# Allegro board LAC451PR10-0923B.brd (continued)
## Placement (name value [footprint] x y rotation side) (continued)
H7  -  [H_3P2]  234.75 97.85 0 top
H8  -  [H_3P2]  252.84 78.4 0 top
H10  H3P5  [H_3P5]  202.39 94.48 0 top
H11  -  [H_2P4]  287.35 87.75 0 top
H12  -  [H_2P5]  298.75 39.26 0 top
H13  -  [H_2P4]  300.75 10.65 0 top
H14  -  [H_2P4]  76.75 40.35 0 top
H15  -  [H_2P5]  6.75 39.26 180 bottom
H16  -  [H_2P5]  2.25 46.15 180 bottom
H17  -  [H_2P8]  2.75 53.15 180 bottom
H18  -  [H_2P4]  54.75 138.55 0 top
H19  -  [H_2P4]  120.25 135.15 0 top
H20  -  [H_2P4]  185.25 135.15 0 top
H21  -  [H_2P4]  250.75 139.45 0 top
H22  -  [H_2P4]  301.75 129.65 0 top
H23  -  [H_4P4]  152.75 119.15 0 top
H24  -  [H_2P4]  264.75 39.75 0 top
H25  -  [H_4P4]  157.1 39.2 0 top
H26  -  [H_2P8]  34.75 39.75 0 top
H27  -  [H_3P5]  69.25 85.65 0 top
H28  -  [H_2P3]  236.75 38.04 0 top
H29  -  [H_0P7N]  300.45 124.17 0 top
H30  -  [H_0P9N]  287.4 114.97 0 top
JAPS1  ACES_50506-01841-P01  [ACES_50506-01841-P01_18P-NPM]  183.56 62.77 0 top
JDEG1  ACES_50521-01041-P01  [ACES_50521-01041-P01_10P]  277.6 11.87 270 top
JDIMM1  LOTES_ADDR0107-P005A  [LOTES_ADDR0107-P005A_260P-T]  83.37 49.85 180 bottom
JDIMM2  LOTES_ADDR0107-P005A  [LOTES_ADDR0107-P005A_260P-T]  163.98 49.85 180 bottom
JDOCK1  JAE_WD2F144WBHR500-DT~D  [JAE_WD2F144WBHR500-DT_144P]  134 130.55 0 bottom
JEDP1  ACES_50398-04041-001  [ACES_50398-04041-001_40P]  101.47 117.86 235 bottom
JFAN1  ACES_50271-0040N-001  [ACES_50271-0040N-001_4P]  78.85 97.54 110 bottom
JHDMI1  CONCR_099BKAC19YBLCNF  [CONCR_099BKAC19YBLCNF_19P]  231.8 133.37 0 bottom
JHP1  SINGA_2SJ3095-022111F  [SINGA_2SJ3095-022111F_6P-T]  293 52.52 90 bottom
JIR1  E-T_4251K-F06N-40L  [E-T_4251K-F06N-40L_6P]  54.45 134.05 180 bottom
JKBTP1  ACES_50506-02041-P01  [ACES_50506-02041-P01_20P]  279.8 3.77 90 bottom
JLED1  ACES_50209-00801-001  [ACES_50209-00801-001_8P-T]  289.39 20.75 270 bottom
JLOM1  SANTA_130456-511  [SANTA_130456-511_13P-T]  271.88 129.43 0 bottom
JLPDE1  HB_A531015-SCHR21  [HB_A531015-SCHR21_10P]  256.5 41.6 180 bottom
JMDP1  ACON_MAR2E-2061800~D  [ACON_MAR2E-2061800_20P]  211.65 132.69 180 bottom
JNGFF1  CONCR_213AAAA32FA  [CONCR_213AAAA32FA_67P]  243.6 44.87 0 bottom
JNGFF2  BELLW_80149-3221  [BELLW_80149-3221_67P]  280.28 88.6 90 bottom
JNGFF3  BELLW_80159-2242  [BELLW_80159-2242_67P-T-S]  25.45 34.79 180 bottom
JRTC1  TYCO_2-1775293-2~D  [TYCO_2-1775293-2_2P]  277.38 18.66 180 bottom
JSD1  T-SOL_156-2000302608_NR  [T-SOL_156-2000302608_19P_NR]  273.58 75.5 270 bottom
JSIM1  T-SOL_5-991503004000-6  [T-SOL_5-991503004000-6_8P-T]  290.08 122.02 270 bottom
JSPI1  E-T_6705K-Y20N-00L  [E-T_6705K-Y20N-00L_20P]  199.9 79.61 0 bottom
JSPK1  ACES_50279-0040N-001  [ACES_50279-0040N-001_4P]  288.21 33.97 270 bottom
JTAG1  @SHORT PADS~D  [SHORTPADS]  261.72 78.39 90 top
JUSB1  ACON_TARAV-9R1U91  [ACON_TARAV-9R1U91_9P]  71.75 129.37 0 bottom
JUSB2  ACON_TARAV-9R1U91  [ACON_TARAV-9R1U91_9P]  94.75 129.37 0 bottom
JUSB3  SINGA_2UB4008-900101F  [SINGA_2UB4008-900101F_9P]  290.09 94.5 270 bottom
JUSH1  E-T_6705K-Y26N-00L  [E-T_6705K-Y26N-00L_26P]  296.9 8.43 180 bottom
JXDP1  SAMTE_BSH-030-01-L-D-A  [SAMTE_BSH-030-01-L-D-A_60P]  118.39 126.21 0 bottom
LA2  BLM15BD601SN1D_2P  [MURAT_BLM15BD601SN1D_2P]  283.57 53.25 0 top
LA3  BLM15BD601SN1D_2P  [MURAT_BLM15BD601SN1D_2P]  283.57 45.12 0 top
LA5  BLM15PX600SN1D_2P  [MURAT_BLM15PX600SN1D_2P]  295.55 67.55 0 top
LA6  BLM15PX330SN1D_2P  [MURAT_BLM15PX330SN1D_2P]  281.15 39.78 270 top
LA7  BLM15PX330SN1D_2P  [MURAT_BLM15PX330SN1D_2P]  281.15 33.19 90 top
LA8  BLM15PX330SN1D_2P  [MURAT_BLM15PX330SN1D_2P]  281.15 32.16 270 top
LA9  BLM15PX330SN1D_2P  [MURAT_BLM15PX330SN1D_2P]  281.15 25.69 90 top
LA10  BLM15PX330SN1D_2P  [MURAT_BLM15PX330SN1D_2P]  283.57 52.1 0 top
LA11  BLM15PX330SN1D_2P  [MURAT_BLM15PX330SN1D_2P]  283.57 47.15 0 top
LC1  BLM15HG601SN1D_2P  [MURAT_BLM15HG601SN1D_2P]  190.74 87.9 270 top
LC2  BLM15HG601SN1D_2P  [MURAT_BLM15HG601SN1D_2P]  193.52 95.68 90 top
LED3  LTW-C193DC-C_WHITE  [LED_LTW-C193DC-C_2P]  294.29 120.3 0 top
LI3  EXC24CQ900U_4P  [PANAS_EXC24CQ900U_4P]  69.38 120.01 180 top
LI4  EXC24CQ900U_4P  [PANAS_EXC24CQ900U_4P]  83.49 122.43 180 top
LI7  EXC24CQ900U_4P  [PANAS_EXC24CQ900U_4P]  284.63 100.3 90 top
LL1  4.7UH_BRC2012T4R7MD_20%  [TAIYO_BRC2012T4R7MD_2P]  266.42 93.15 90 top
LV1  BLM15BB221SN1D_2P  [MURAT_BLM15BB221SN1D_2P]  95.55 110.36 325 top
LV3  HCM1012GH900BP_4P  [TAIYO_MCF12102G900-T_4P-NPM]  232.59 127.68 90 top
LV6  HCM1012GH900BP_4P  [TAIYO_MCF12102G900-T_4P-NPM]  234.39 127.68 90 top
LV9  HCM1012GH900BP_4P  [TAIYO_MCF12102G900-T_4P-NPM]  230.8 127.67 90 top
LV12  HCM1012GH900BP_4P  [TAIYO_MCF12102G900-T_4P-NPM]  236.2 127.68 90 top
LV22  BLM15PX181SN1D_2P  [MURAT_BLM15PX181SN1D_2P]  219.24 109.24 180 bottom
LV23  BLM15PX181SN1D_2P  [MURAT_BLM15PX181SN1D_2P]  219.24 110.32 180 bottom
LV24  BLM15PX181SN1D_2P  [MURAT_BLM15PX181SN1D_2P]  221.08 119.42 90 bottom
LV25  BLM15PX181SN1D_2P  [MURAT_BLM15PX181SN1D_2P]  221.08 117.77 90 bottom
LV27  EXC24CQ900U_4P  [PANAS_EXC24CQ900U_4P]  110.52 120.79 90 bottom
LZ1  EXC24CQ900U_4P  [PANAS_EXC24CQ900U_4P]  96.79 113.17 55 top
NOREF  -  []  137.4 153.98 0 top
NOREF#2  -  []  120.25 135.15 0 top
NOREF#3  -  []  125.77 188.5 0 top
NOREF#4  -  []  123.79 104.27 0 top
NOREF#5  -  []  202.39 94.48 0 top
NOREF#6  -  []  252.84 78.4 0 top
NOREF#7  -  []  2.75 53.15 0 top
NOREF#8  -  []  301.75 129.65 0 top
NOREF#9  -  []  54.75 138.55 0 top
NOREF#10  -  []  2.25 46.15 0 top
NOREF#11  -  []  123.79 82.13 0 top
NOREF#12  -  []  142.62 65.03 270 top
NOREF#13  -  []  250.75 139.45 0 top
NOREF#14  -  []  6.75 39.26 0 top
NOREF#15  -  []  183.61 104.27 0 top
NOREF#16  -  []  168.94 55.49 0 top
NOREF#17  -  []  185.25 135.15 0 top
NOREF#18  -  []  183.61 82.13 0 top
NOREF#19  -  []  234.75 97.85 0 top
NOREF#20  -  []  103.11 92.87 0 top
NOREF#21  -  []  298.75 39.26 0 top
NOREF#22  -  []  137.23 281.75 0 top
NOREF#23  -  []  300.75 10.65 0 top
NOREF#24  -  []  287.35 87.75 0 top
NOREF#25  -  []  213.61 96.07 270 top
NOREF#26  -  []  176.25 112.88 0 top
NOREF#27  -  []  144.79 -7.08 0 top
NOREF#28  -  []  76.75 40.35 0 top
NOREF#29  -  []  107.87 58.82 90 top
NOREF#30  -  []  152.75 119.15 0 top
NOREF#31  -  []  197.93 69.03 180 bottom
NOREF#32  -  []  122.38 72.75 180 bottom
NOREF#33  -  []  174.41 57.88 180 bottom
PBATT1  DEREN_40-42251-01001RHF  [DEREN_40-42251-01001RHF_10P-T]  67.87 55.92 235 bottom
PC1  1000P_0603_50V7K  [C_0603]  76.62 102.9 0 top
PC2  1U_0603_10V6K  [C_0603]  284.03 17.98 180 bottom
PC3  2200P_0402_50V7K  [C_0402]  71.27 56.42 0 top
PC4  1500P_0402_50V7K  [C_0402]  72.62 44.53 90 top
PC5  0.022U_0805_50V7K  [C_0805]  69.73 97.95 0 top
PC6  0.1U_0603_25V7K  [C_0603]  71.28 99.48 180 top
PC7  10U_0805_25V6K  [C_0805]  70.08 92.07 270 top
PC100  0.1U_0402_25V6  [C_0402]  218.2 79.69 180 bottom
PC101  0.1U_0402_10V7K  [C_0402]  204.94 81.81 90 top
PC102  0.1U_0603_25V7K  [C_0603]  220.1 90.45 180 top
PC103  2200P_0402_50V7K  [C_0402]  218.2 78.8 180 bottom
PC104  10U_0805_25V6K  [C_0805]  218.04 81.9 180 bottom
PC105  10U_0805_25V6K  [C_0805]  218.04 81.9 180 top
PC106  22U_0805_6.3V6M  [C_0805]  220.65 101.29 0 top
PC107  22U_0805_6.3V6M  [C_0805]  220.65 99.55 0 top
PC108  22U_0805_6.3V6M  [C_0805]  220.66 97.81 0 bottom
PC109  22U_0805_6.3V6M  [C_0805]  220.65 99.55 0 bottom
PC110  22U_0805_6.3V6M  [C_0805]  220.65 101.29 0 bottom
PC111  4.7U_0603_6.3V6K  [C_0603]  214.46 85.8 270 top
PC112  680P_0603_50V7K  [C_0603]  217.35 84.87 180 top
PC113  1000P_0402_50V7K  [C_0402]  213.29 85 180 bottom
PC114  0.1U_0603_25V7K  [C_0603]  213.52 88.25 180 bottom
PC115  0.1U_0402_25V6  [C_0402]  209.61 81.77 180 bottom
PC116  2200P_0402_50V7K  [C_0402]  209.59 80.87 180 bottom
PC117  10U_0805_25V6K  [C_0805]  210.96 83.09 180 bottom
PC118  10U_0805_25V6K  [C_0805]  210.96 83.09 180 top
PC119  4.7U_0603_6.3V6K  [C_0603]  206.79 89.54 180 bottom
PC120  22U_0805_6.3V6M  [C_0805]  207.64 102.8 180 top
PC121  22U_0805_6.3V6M  [C_0805]  207.64 101.05 180 top
PC122  22U_0805_6.3V6M  [C_0805]  207.64 99.31 180 bottom
PC123  22U_0805_6.3V6M  [C_0805]  207.64 101.05 180 bottom
PC124  22U_0805_6.3V6M  [C_0805]  207.64 102.8 180 bottom
PC125  680P_0603_50V7K  [C_0603]  210.11 86.39 270 top
PC126  4.7U_0603_6.3V6K  [C_0603]  206.12 88.26 180 bottom
PC127  1000P_0402_50V7K  [C_0402]  204.77 85.4 90 bottom
PC128  4.7U_0402_6.3V6M  [C_0402]  206.09 82.68 180 bottom
PC201  10U_0805_25V6K  [C_0805]  72.36 62.1 270 top
PC202  10U_0805_25V6K  [C_0805]  70.58 62.1 270 top
PC203  2200P_0402_50V7K  [C_0402]  74.78 62.09 270 top
PC204  0.1U_0402_25V6  [C_0402]  73.76 62.09 270 top
PC205  0.22U_0603_16V7K  [C_0603]  78.08 71.15 90 bottom
PC206  22U_0603_6.3V6M  [C_0603]  73.06 72.93 180 bottom
PC207  1U_0603_10V6K  [C_0603]  79.38 78.76 270 bottom
PC209  1U_0603_10V6K  [C_0603]  79.67 75.2 270 bottom
PC210  0.033U_0402_16V7K  [C_0402]  74.13 76.42 0 top
PC211  680P_0603_50V7K  [C_0603]  76.81 69.44 0 top
PC212  100P_0402_50V8J  [C_0402]  75.85 79.49 90 top
PC213  .1U_0402_16V7K  [C_0402]  76.93 78.22 270 top
PC214  .1U_0402_16V7K  [C_0402]  76.05 78.2 270 top
PC215  22U_0603_6.3V6M  [C_0603]  75.54 58.19 270 bottom
PC216  22U_0603_6.3V6M  [C_0603]  74.27 59.03 270 top
PC217  22U_0603_6.3V6M  [C_0603]  74.27 59.03 270 bottom
PC218  22U_0603_6.3V6M  [C_0603]  75.54 58.19 270 top
PC219  22U_0603_6.3V6M  [C_0603]  76.81 58.19 270 bottom
PC220  22U_0603_6.3V6M  [C_0603]  76.81 58.19 270 top
PC301  0.1U_0402_25V6  [C_0402]  223.94 82.13 90 top
PC302  680P_0603_50V7K  [C_0603]  221.78 86.65 0 bottom
PC303  2200P_0402_50V7K  [C_0402]  223.05 82.13 90 top
PC304  0.1U_0603_25V7K  [C_0603]  227.87 82.58 180 bottom
PC305  10U_0805_25V6K  [C_0805]  223.77 80.87 180 top
PC306  10U_0805_25V6K  [C_0805]  223.77 79.16 180 top
PC307  330P_0402_50V7K  [C_0402]  231.49 84.57 270 top
PC308  47U_0805_6.3V6M  [C_0805]  224.08 89.71 180 top
PC309  47U_0805_6.3V6M  [C_0805]  224.08 87.93 180 top
PC310  22UF_0805_6.3V6M  [C_0805]  222.43 88.91 180 bottom
PC311  22UF_0805_6.3V6M  [C_0805]  222.82 90.71 180 bottom
PC312  4.7U_0603_6.3V6K  [C_0603]  228.95 80.74 270 top
PC313  4.7U_0603_6.3V6K  [C_0603]  229.52 82.14 0 top
PC401  470P_0402_50V7K  [C_0402]  240.7 47.04 270 top
PC402  0.1U_0402_25V6  [C_0402]  242.48 43.21 270 top
PC403  10U_0603_10V6M  [C_0603]  237.63 41.94 180 bottom
PC404  10U_0603_10V6M  [C_0603]  237.63 41.94 180 top
PC406  22U_0603_6.3V6M  [C_0603]  239.43 50.83 0 top
PC407  22U_0603_6.3V6M  [C_0603]  238.02 50.31 0 bottom
PC408  0.1U_0402_25V6  [C_0402]  239.63 42.13 270 top
PC409  2200P_0402_50V7K  [C_0402]  239.63 42.13 270 bottom
PC410  470P_0402_50V7K  [C_0402]  234.05 42.71 180 top
PC411  0.1U_0402_25V6  [C_0402]  243.49 95.21 90 top
PC412  10U_0603_10V6M  [C_0603]  245.15 94.08 0 top
PC413  10U_0603_10V6M  [C_0603]  245.15 92.81 0 top
PC415  22U_0603_6.3V6M  [C_0603]  236.95 89.25 270 top
PC416  22U_0603_6.3V6M  [C_0603]  238.22 89.25 270 top
PC417  0.1U_0402_25V6  [C_0402]  245.64 91.66 0 top
PC418  2200P_0402_50V7K  [C_0402]  245.64 90.78 0 top
PC419  470P_0402_50V7K  [C_0402]  239.74 94.78 0 top
PC420  470P_0402_50V7K  [C_0402]  241.32 87.45 0 top
PC422  22U_0603_6.3V6M  [C_0603]  239.43 49.56 0 top
PC424  22U_0603_6.3V6M  [C_0603]  235.68 88.43 270 top
PC501  22U_0603_6.3V6M  [C_0603]  283.69 4.54 270 top
PC502  22U_0603_6.3V6M  [C_0603]  293.22 3.02 90 top
PC503  68P_0402_50V8J  [C_0402]  292.71 7.6 270 top
PC504  22U_0603_6.3V6M  [C_0603]  282.42 4.54 270 top
PC505  0.1U_0402_16V7K  [C_0402]  287.67 6.8 90 top
PC506  680P_0402_50V7K  [C_0402]  291.11 3.34 0 top
PC507  1U_0402_6.3V6K  [C_0402]  289.1 16.93 180 top
PC508  4.7U_0805_6.3V6K  [C_0805]  290.97 19.85 0 top
PC509  0.01U_0402_25V7K  [C_0402]  297.79 16.87 270 top
PC510  .1U_0402_16V7K  [C_0402]  289.1 15.27 180 top
PC511  22U_0805_6.3V6M  [C_0805]  295.55 19.86 180 top
PC601  680P_0402_50V7K  [C_0402]  89.65 94.4 180 top
PC602  0.1U_0402_25V6  [C_0402]  82.71 86.15 270 bottom
PC603  1U_0603_10V6K  [C_0603]  84.68 88.49 270 bottom
PC604  0.22U_0603_25V7K  [C_0603]  82.65 89.76 90 bottom
PC605  47P_0402_50V8J~D  [C_0402]  79.98 87.49 270 top
PC606  100U_D_20VM_R55M  [C_D]  103.98 108.37 0 bottom
PC608  10U_0805_25V6K  [C_0805]  129.8 111.67 0 top
PC611  0.22U_0603_16V7K  [C_0603]  128.18 113.83 180 top
PC612  10U_0805_25V6K  [C_0805]  129.8 110.84 0.1 bottom
PC613  330P_0402_50V7K  [C_0402]  85.38 86.09 270 bottom
PC614  2200P_0402_50V7K  [C_0402]  88.05 85.17 90 bottom
PC616  33P_0402_50V8J  [C_0402]  86.27 86.09 270 bottom
PC617  1200P_0402_50V7K  [C_0402]  87.35 82.34 270 top
PC618  330P_0402_50V7K  [C_0402]  82.83 82.46 0 bottom
PC619  0.01U_0402_50V7K  [C_0402]  82.83 83.35 0 bottom
PC620  0.082U_0402_16V7K  [C_0402]  84.62 82.44 90 bottom
PC621  680P_0402_50V7K  [C_0402]  84.68 81.43 90 top
PC622  680P_0603_50V7K  [C_0603]  133.07 117 180 top
PC624  0.033U_0402_16V7K  [C_0402]  84.49 80.76 270 bottom
PC625  330P_0402_50V7K  [C_0402]  88.92 86.58 0 bottom
PC626  0.047U_0402_25V7K  [C_0402]  83.6 80.76 270 bottom
PC627  2200P_0402_50V7K  [C_0402]  88.24 82.32 90 top
PC628  10P_0402_50V8J  [C_0402]  86.9 90.53 270 bottom
PC629  2200P_0402_50V7K  [C_0402]  89.76 90.22 270 bottom
PC630  2200P_0402_50V7K  [C_0402]  91.73 91.27 90 top
PC631  1200P_0402_50V7K  [C_0402]  85.11 89.57 0 bottom
PC632  2200P_0402_25V7K  [C_0402]  86.01 92.54 90 top
PC633  6800P_0402_25V7K  [C_0402]  85.95 92.6 90 bottom
PC636  33P_0402_50V8J  [C_0402]  88.92 87.47 0 bottom
PC637  0.033U_0402_16V7K  [C_0402]  84.17 92.6 90 bottom
PC639  1500P_0402_50V7K  [C_0402]  92.67 88.62 0 top
PC640  2200P_0402_50V7K  [C_0402]  87.81 93.51 180 top
PC641  .1U_0402_16V7K  [C_0402]  81.82 79.84 90 bottom
PC642  0.033U_0402_16V7K  [C_0402]  91.72 92.17 0 bottom
PC643  330P_0402_50V7K  [C_0402]  87.79 90.53 270 bottom
PC644  .1U_0402_16V7K  [C_0402]  83.28 93.32 270 bottom
PC645  .1U_0402_16V7K  [C_0402]  92.63 93.06 180 bottom
PC646  0.047U_0402_25V7K  [C_0402]  91.72 91.28 0 bottom
PC647  680P_0402_50V7K  [C_0402]  94.27 87.87 270 bottom
PC649  0.01U_0402_50V7K  [C_0402]  88.67 92.62 0 bottom
PC650  0.082U_0402_16V7K  [C_0402]  86.89 92.62 0 bottom
PC651  330P_0402_50V7K  [C_0402]  93.52 89.51 180 top
PC652  330P_0402_50V7K  [C_0402]  86.89 93.51 0 bottom
PC653  0.082U_0402_16V7K  [C_0402]  91.73 89.49 90 top
PC654  0.01U_0402_50V7K  [C_0402]  93.52 90.39 180 top
PC655  0.22U_0603_16V7K  [C_0603]  101.95 107.1 270 top
PC656  10U_0805_25V6K  [C_0805]  102.5 97.89 0 top
PC657  10U_0805_25V6K  [C_0805]  100.01 101.76 180 bottom
PC658  10U_0805_25V6K  [C_0805]  102.5 98.9 0 bottom
PC659  0.1U_0402_25V6K~D  [C_0402]  99.62 104.94 180 bottom
PC660  2200P_0402_50V7K  [C_0402]  99.62 104.05 180 bottom
PC661  1U_0402_10V6K  [C_0402]  107.61 104.49 0 bottom
PC662  680P_0603_50V7K  [C_0603]  105.95 105.7 180 top
PC671  0.22U_0603_16V7K  [C_0603]  88.03 80.26 0 top
PC672  10U_0805_25V6K  [C_0805]  89.61 77.58 180 bottom
PC673  10U_0805_25V6K  [C_0805]  89.61 77.58 180 top
PC677  1U_0402_10V6K  [C_0402]  96.43 82.67 0 bottom
PC678  680P_0603_50V7K  [C_0603]  96.59 79.43 270 top
PC679  1000P_0402_50V7K  [C_0402]  89.23 78.99 180 bottom
PC680  1000P_0402_50V7K  [C_0402]  99.62 103.16 180 bottom
PC685  1U_0402_10V6K  [C_0402]  127.43 116.49 180 bottom
PC686  10P_0402_50V8J  [C_0402]  99.62 105.83 180 bottom
PC688  10P_0402_50V8J  [C_0402]  89.23 79.88 180 bottom
PC801  10U_0805_25V6K  [C_0805]  32.36 46.81 90 top
PC802  0.1U_0603_25V7K  [C_0603]  13.88 54.64 0 bottom
PC803  10U_0805_25V6K  [C_0805]  41.97 42.26 180 bottom
PC804  10U_0805_25V6K  [C_0805]  40.99 40.83 270 bottom
PC805  22U_0805_25V6M  [C_0805]  40.87 46.62 90 bottom
PC806  10U_0805_25V6K  [C_0805]  41.97 42.26 180 top
PC807  10U_0805_25V6K  [C_0805]  40.99 40.83 270 top
PC808  1U_0603_25V6K  [C_0603]  54.02 54.33 0 bottom
PC809  0.1U_0402_25V6  [C_0402]  56.37 54.53 270 bottom
PC810  0.1U_0402_25V6  [C_0402]  55.43 53.25 180 bottom
PC811  10U_0805_25V6K  [C_0805]  42.77 40.83 270 top
PC812  10U_0805_25V6K  [C_0805]  42.77 40.83 270 bottom
PC813  1U_0603_10V6K  [C_0603]  53.25 51.28 270 top
PC814  10U_0805_25V6K  [C_0805]  57.92 50.74 0 top
PC815  0.1U_0402_25V6  [C_0402]  56.63 55.41 180 bottom
PC816  2200P_0402_50V7K  [C_0402]  60.47 48.48 0 top
PC817  0.1U_0402_25V6  [C_0402]  60.47 47.6 0 top
PC818  22U_0805_25V6M  [C_0805]  59.47 42.86 270 top
PC819  22U_0805_25V6M  [C_0805]  61.25 42.86 270 top
PC820  22U_0805_25V6M  [C_0805]  59.86 44.46 0 top
PC821  0.047U_0603_16V7K  [C_0603]  55.79 51.28 270 top
PC822  22U_0805_25V6M  [C_0805]  59.88 46.24 0 top
PC823  100P_0402_50V8J  [C_0402]  57.31 57.17 90 bottom
PC824  100P_0402_50V8J  [C_0402]  56.42 57.17 90 bottom
PC825  0.1U_0603_25V7K  [C_0603]  30.71 46.96 90 bottom
PC826  10U_0805_25V6K  [C_0805]  30.58 46.81 90 top
PC827  10U_0805_25V6K  [C_0805]  32.36 46.81 90 bottom
PC828  1U_0603_25V6K  [C_0603]  50.28 57.59 180 top
PC829  0.1U_0402_25V6  [C_0402]  53.01 54.83 180 bottom
PC830  0.1U_0402_25V6  [C_0402]  51.23 54.83 90 bottom
PC831  0.1U_0402_25V6  [C_0402]  52.09 55.72 0 bottom
PC832  1000P_0603_50V7K  [C_0603]  50.52 39.72 90 top
PC833  100P_0402_50V8J  [C_0402]  59.28 59.52 90 top
PC834  100P_0402_50V8J  [C_0402]  59.28 62.34 270 top
PC835  22U_0805_25V6M  [C_0805]  40.57 45.73 90 top
PC901  0.1U_0402_25V4Z~D  [C_0402]  93.37 68.61 0 top
PC902  0.47U_0805_25V6K  [C_0805]  6.16 48.81 270 bottom
PC903  0.1U_0402_10V7K  [C_0402]  68.04 72.25 270 top
PC904  1500P_0402_50V7K  [C_0402]  15.03 40.93 180 top
PC905  0.1U_0402_10V7K  [C_0402]  104.11 70.06 90 top
PC906  0.1U_0603_25V7K  [C_0603]  86.01 64.55 180 top
PC907  0.047U_0603_25V7M  [C_0603]  93.38 67.47 0 top
PC908  0.1U_0603_25V7K  [C_0603]  87.22 64.11 270 top
PC1001  22U_0603_6.3V6M  [C_0603]  113.83 107.48 180 bottom
PC1002  22U_0603_6.3V6M  [C_0603]  121.32 112.87 180 top
PC1003  22U_0603_6.3V6M  [C_0603]  116.56 97.13 270 bottom
PC1004  22U_0603_6.3V6M  [C_0603]  154.12 90.29 90 top
PC1005  22U_0603_6.3V6M  [C_0603]  113.83 106.21 180 bottom
PC1006  22U_0603_6.3V6M  [C_0603]  150.5 90.29 90 top
PC1007  22U_0603_6.3V6M  [C_0603]  150.4 96.52 270 top
PC1008  22U_0603_6.3V6M  [C_0603]  121.32 110.33 180 bottom
PC1009  22U_0603_6.3V6M  [C_0603]  155.31 96.52 270 top
PC1010  22U_0603_6.3V6M  [C_0603]  121.32 114.14 180 top
PC1011  22U_0603_6.3V6M  [C_0603]  117.83 97.13 270 bottom
PC1012  22U_0603_6.3V6M  [C_0603]  155.33 90.29 90 top
PC1013  22U_0603_6.3V6M  [C_0603]  151.7 90.29 90 top
PC1014  22U_0603_6.3V6M  [C_0603]  114.91 91.92 90 bottom
PC1015  22U_0603_6.3V6M  [C_0603]  113.26 89.63 270 bottom
PC1016  22U_0603_6.3V6M  [C_0603]  129.61 97.78 270 top
PC1017  22U_0603_6.3V6M  [C_0603]  114.91 89.63 270 bottom
PC1018  22U_0603_6.3V6M  [C_0603]  113.26 91.92 90 bottom
PC1019  22U_0603_6.3V6M  [C_0603]  114.91 91.92 90 top
PC1020  22U_0603_6.3V6M  [C_0603]  145.34 96.01 270 top
PC1021  22U_0603_6.3V6M  [C_0603]  146.55 96.01 270 top
PC1022  22U_0603_6.3V6M  [C_0603]  116.56 91.92 90 bottom
PC1023  22U_0603_6.3V6M  [C_0603]  128.04 95.36 270 top
PC1024  22U_0603_6.3V6M  [C_0603]  133.59 90.4 0 top
PC1025  22U_0603_6.3V6M  [C_0603]  136.13 90.37 0 top
PC1026  22U_0603_6.3V6M  [C_0603]  146.53 93.21 270 top
PC1027  22U_0603_6.3V6M  [C_0603]  116.56 89.63 270 bottom
PC1028  22U_0603_6.3V6M  [C_0603]  139.25 93.61 270 top
PC1029  22U_0603_6.3V6M  [C_0603]  139.25 95.96 270 top
PC1030  1U_0201_6.3V6M  [C_0201]  149.14 92.95 180 top
PC1031  1U_0201_6.3V6M  [C_0201]  155.72 100.11 180 top
PC1032  1U_0201_6.3V6M  [C_0201]  157.41 100.97 180 top
PC1033  1U_0201_6.3V6M  [C_0201]  156.39 98.81 0 top
PC1034  1U_0201_6.3V6M  [C_0201]  154.89 98.65 0 top
PC1035  1U_0201_6.3V6M  [C_0201]  149.14 93.52 180 top
PC1036  1U_0201_6.3V6M  [C_0201]  149.11 98.67 180 top
PC1037  1U_0201_6.3V6M  [C_0201]  154.28 89.49 180 top
PC1038  1U_0201_6.3V6M  [C_0201]  154.94 89.52 0 top
PC1039  1U_0201_6.3V6M  [C_0201]  149.14 91.23 180 top
PC1040  1U_0201_6.3V6M  [C_0201]  143.27 98.76 180 top
PC1041  1U_0201_6.3V6M  [C_0201]  134.42 92.4 270 top
PC1042  1U_0201_6.3V6M  [C_0201]  136.36 95.08 270 top
PC1043  1U_0201_6.3V6M  [C_0201]  137.09 92.41 270 top
PC1044  1U_0201_6.3V6M  [C_0201]  137.65 94.42 90 top
PC1045  1U_0201_6.3V6M  [C_0201]  146.66 98.8 0 top
PC1046  1U_0201_6.3V6M  [C_0201]  137.65 96.93 270 top
PC1047  1U_0201_6.3V6M  [C_0201]  141.43 98.79 180 top
PC1048  1U_0201_6.3V6M  [C_0201]  139.23 98.79 0 top
PC1049  1U_0201_6.3V6M  [C_0201]  134.95 94.62 270 top
PC1050  1U_0201_6.3V6M  [C_0201]  156.28 92.77 0 top
PC1051  1U_0201_6.3V6M  [C_0201]  152.71 98.71 0 top
PC1052  1U_0201_6.3V6M  [C_0201]  158.01 100.97 0 top
PC1053  1U_0201_6.3V6M  [C_0201]  150.16 100.83 180 top
PC1054  1U_0201_6.3V6M  [C_0201]  152.95 100.96 180 top
PC1055  1U_0201_6.3V6M  [C_0201]  145.08 98.8 180 top
PC1056  1U_0201_6.3V6M  [C_0201]  136.36 96.83 270 top
PC1057  22U_0603_6.3V6M  [C_0603]  158.87 94.6 180 top
PC1058  22U_0603_6.3V6M  [C_0603]  141.2 112.62 270 top
PC1059  22U_0603_6.3V6M  [C_0603]  141.2 112.62 270 bottom
PC1060  22U_0603_6.3V6M  [C_0603]  139.93 112.62 270 top
PC1061  22U_0603_6.3V6M  [C_0603]  113.85 107.42 180 top
PC1062  330U_D2_2.5VM_R9M  [C_D2]  117.07 107.77 90 bottom
PC1063  330U_D2_2.5VM_R9M  [C_D2]  117.07 84.77 270 bottom
PC1064  22U_0603_6.3V6M  [C_0603]  155.36 94.1 270 top
PC1065  22U_0603_6.3V6M  [C_0603]  121.32 112.87 180 bottom
PC1066  22U_0603_6.3V6M  [C_0603]  154.09 96.52 270 top
PC1067  22U_0603_6.3V6M  [C_0603]  121.32 111.6 180 bottom
PC1068  22U_0603_6.3V6M  [C_0603]  151.68 94.06 270 top
PC1069  22U_0603_6.3V6M  [C_0603]  152.89 94.06 270 top
PC1070  22U_0603_6.3V6M  [C_0603]  154.1 94.06 270 top
PC1071  22U_0603_6.3V6M  [C_0603]  152.91 90.29 90 top
PC1072  22U_0603_6.3V6M  [C_0603]  150.48 94.06 270 top
PC1073  22U_0603_6.3V6M  [C_0603]  121.32 111.6 180 top
PC1074  22U_0603_6.3V6M  [C_0603]  152.87 96.52 270 top
PC1075  22U_0603_6.3V6M  [C_0603]  115.29 97.13 270 top
PC1076  22U_0603_6.3V6M  [C_0603]  113.83 108.75 180 bottom
PC1077  22U_0603_6.3V6M  [C_0603]  113.83 106.21 180 top
PC1078  22U_0603_6.3V6M  [C_0603]  121.32 114.14 180 bottom
PC1079  22U_0603_6.3V6M  [C_0603]  123.73 110.59 180 bottom
PC1080  22U_0603_6.3V6M  [C_0603]  116.56 97.13 270 top
PC1081  22U_0603_6.3V6M  [C_0603]  114.02 97.13 270 bottom
PC1082  22U_0603_6.3V6M  [C_0603]  115.29 97.13 270 bottom
PC1083  1U_0201_6.3V6M  [C_0201]  156.97 99.53 0 top
PC1084  1U_0201_6.3V6M  [C_0201]  151.23 98.71 0 top
PC1085  1U_0201_6.3V6M  [C_0201]  156.28 90.48 0 top
PC1086  1U_0201_6.3V6M  [C_0201]  149.14 90.66 180 top
PC1087  1U_0201_6.3V6M  [C_0201]  152.13 89.45 180 top
PC1088  1U_0201_6.3V6M  [C_0201]  153.47 100.07 0 top
PC1089  1U_0201_6.3V6M  [C_0201]  145.73 89.53 180 top
PC1090  1U_0201_6.3V6M  [C_0201]  156.97 100.11 0 top
PC1091  1U_0201_6.3V6M  [C_0201]  156.28 91.62 0 top
PC1092  1U_0201_6.3V6M  [C_0201]  156.28 92.2 0 top
PC1093  1U_0201_6.3V6M  [C_0201]  156.28 93.34 0 top
PC1094  1U_0201_6.3V6M  [C_0201]  155.19 100.94 0 top
PC1095  1U_0201_6.3V6M  [C_0201]  153.58 100.95 0 top
PC1096  1U_0201_6.3V6M  [C_0201]  152.88 100.07 180 top
PC1097  1U_0201_6.3V6M  [C_0201]  150.26 100.11 180 top
PC1098  1U_0201_6.3V6M  [C_0201]  149.14 94.09 180 top
PC1099  1U_0201_6.3V6M  [C_0201]  149.14 92.37 180 top
PC1125  1U_0201_6.3V6M  [C_0201]  149.14 91.8 180 top
PC1126  1U_0201_6.3V6M  [C_0201]  156.28 91.05 0 top
PC1127  330U_D2_2.5VM_R9M  [C_D2]  112.58 113.19 180 bottom
PC1128  330U_D2_2.5VM_R9M  [C_D2]  112.37 84.77 270 bottom
PC1129  22U_0603_6.3V6M  [C_0603]  145.32 93.21 270 top
PC1130  22U_0603_6.3V6M  [C_0603]  140.5 95.96 270 top
PC1131  22U_0603_6.3V6M  [C_0603]  131.13 92.98 270 top
PC1132  22U_0603_6.3V6M  [C_0603]  140.5 93.61 270 top
PC1133  22U_0603_6.3V6M  [C_0603]  128.04 97.79 270 top
PC1134  22U_0603_6.3V6M  [C_0603]  132.67 95.37 270 top
PC1135  22U_0603_6.3V6M  [C_0603]  129.61 95.37 270 top
PC1136  22U_0603_6.3V6M  [C_0603]  133.69 89.16 270 top
PC1137  22U_0603_6.3V6M  [C_0603]  114.91 89.63 270 top
PC1138  22U_0603_6.3V6M  [C_0603]  131.13 95.37 270 top
PC1139  22U_0603_6.3V6M  [C_0603]  139.93 114.78 90 top
PC1140  22U_0603_6.3V6M  [C_0603]  141.2 114.78 90 top
PC1141  22U_0603_6.3V6M  [C_0603]  141.2 114.78 90 bottom
PC1142  22U_0603_6.3V6M  [C_0603]  159.7 90.96 180 top
PC1143  22U_0603_6.3V6M  [C_0603]  159.71 89.71 180 top
PC1144  22U_0603_6.3V6M  [C_0603]  158.87 95.8 180 top
PC1145  22U_0603_6.3V6M  [C_0603]  139.93 114.78 90 bottom
PC1146  22U_0603_6.3V6M  [C_0603]  139.93 112.62 270 bottom
PC1147  1U_0201_6.3V6M  [C_0201]  159.47 92.9 180 top
PC1148  1U_0201_6.3V6M  [C_0201]  159.47 93.54 180 top
PC1149  1U_0201_6.3V6M  [C_0201]  160.4 96.6 0 top
PC1150  1U_0201_6.3V6M  [C_0201]  159.5 91.84 0 top
PC1151  1U_0201_6.3V6M  [C_0201]  159.32 99.01 90 top
PC1152  1U_0201_6.3V6M  [C_0201]  160.12 92.79 0 top
PC1153  1U_0201_6.3V6M  [C_0201]  158.73 99.01 90 top
PC1164  1U_0201_6.3V6M  [C_0201]  150.59 98.71 180 top
PC1170  22U_0603_6.3V6M  [C_0603]  151.64 96.52 270 top
PC1171  22U_0603_6.3V6M  [C_0603]  123.73 111.86 180 bottom
PC1172  22U_0603_6.3V6M  [C_0603]  126.15 111.86 180 top
PC1173  22U_0603_6.3V6M  [C_0603]  123.73 111.86 180 top
PC1174  22U_0603_6.3V6M  [C_0603]  126.15 110.59 180 bottom
PC1175  22U_0603_6.3V6M  [C_0603]  118.08 89.63 270 bottom
PC1176  22U_0603_6.3V6M  [C_0603]  118.08 91.92 90 bottom
PC1177  22U_0603_6.3V6M  [C_0603]  132.65 92.93 270 top
PC1178  22U_0603_6.3V6M  [C_0603]  116.56 89.63 270 top
PC1179  22U_0603_6.3V6M  [C_0603]  116.56 91.92 90 top
PC1180  22U_0603_6.3V6M  [C_0603]  128.06 92.98 270 top
PC1181  22U_0603_6.3V6M  [C_0603]  129.6 92.96 270 top
PC1500  1U_0402_6.3V6K  [C_0402]  257.15 46.94 0 top
PC1501  4.7U_0805_6.3V6K  [C_0805]  259.48 45.41 90 top
PC1502  0.01U_0402_25V7K  [C_0402]  251.98 38.97 0 top
PC1503  22U_0805_6.3V6M  [C_0805]  250.68 40.1 90 top
PC1504  .1U_0402_16V7K  [C_0402]  252.87 45.33 180 top
PD1  BAS40CW SOT-323  [BAS40-05W_SC70-3]  283.94 16.11 90 bottom
PD2  -  [TVNST52302AB0_SOT523-3]  67.2 41.53 180 top
PD3  -  [TVNST52302AB0_SOT523-3]  65.12 41.53 180 top
PD4  SDMK0340L-7-F_SOD323-2~D  [RB751V-40_SOD323-2]  69.39 40.42 0 top
PD6  -  [PESD5V0U2BT_SOT23-3]  76.2 111.92 90 top
PD7  -  [PESD5V0U2BT_SOT23-3]  79.27 107.46 0 top
PD801  SDMK0340L-7-F_SOD323-2~D  [SDMK0340L-7-F_SOD323-2]  59.73 56.42 0 top
PD802  SDMK0340L-7-F_SOD323-2~D  [SDMK0340L-7-F_SOD323-2]  59.73 58.2 0 top
PD803  SDMK0340L-7-F_SOD323-2~D  [SDMK0340L-7-F_SOD323-2]  59.73 54.64 0 top
PD901  -  [BAT54CW_SOT323-3]  83.36 74.37 0 top
PD902  -  [PDS5100H-13_POWERDI5-3]  26.75 46.52 180 bottom
PD903  -  [PDS5100H-13_POWERDI5-3]  12.8 49.29 270 top
PD904  SDMK0340L-7-F_SOD323-2~D  [SDMK0340L-7-F_SOD323-2]  12.67 39.98 90 top
PD905  -  [BAT54CW_SOT323-3]  9.49 57.7 90 top
PH601  470K_0402_5%_ TSM0B474J4702RE  [R_0402]  93.25 82.43 180 bottom
PH602  10K_0402_5%_ERTJ0ER103J  [R_0402]  101.66 84.97 0 bottom
PH603  470K_0402_5%_ TSM0B474J4702RE  [R_0402]  108.55 98.46 180 bottom
PH604  10KB_0402_5%_ERTJ0ER103J  [R_0402]  136.43 118.12 270 bottom
PH605  10KB_0402_5%_ERTJ0ER103J  [R_0402]  112.81 96.29 90 bottom
PJP1  PAD-OPEN 1X3M  [JUMP_43X118]  68.43 110.42 90 top
PJP6  PAD-OPEN1X2M  [JUMP_43X79]  297.21 76.76 90 top
PJP9  PAD-OPEN1X1M  [JUMP_43X39]  275.56 71.59 90 top
PJP10  PAD-OPEN1X1M  [JUMP_43X39]  275.69 66.28 270 top
PJP11  PAD-OPEN1X1M  [JUMP_43X39]  221.29 63.57 180 top
PJP12  PAD-OPEN1X2M  [JUMP_43X79]  245.46 50.41 90 top
PJP13  PAD-OPEN1X1M  [JUMP_43X39]  283 112.81 180 top
PJP14  PAD-OPEN1X1M  [JUMP_43X39]  264.69 58.71 0 top
PJP15  PAD-OPEN1X1M  [JUMP_43X39]  263.19 58.71 180 top
PJP16  PAD-OPEN1X1M  [JUMP_43X39]  282.17 11.29 270 top
PJP18  PAD-OPEN1X2M  [JUMP_43X79]  83.41 114.5 270 bottom
PJP19  PAD-OPEN1X1M  [JUMP_43X39]  192.97 82.52 180 top
PJP20  PAD-OPEN1X1M  [JUMP_43X39]  198.27 84.29 0 top
PJP21  PAD-OPEN1X2M  [JUMP_43X79]  83.41 121.79 90 bottom
PJP22  PAD-OPEN1X3M  [JUMP_43X118]  246.23 44.27 270 top
PJP23  PAD-OPEN1X3M  [JUMP_43X118]  283.31 106.17 180 top
PJP25  PAD-OPEN1X1M  [JUMP_43X39]  211.68 105.94 90 top
PJP26  PAD-OPEN1X2M  [JUMP_43X79]  267.5 72.89 90 top
PJP27  PAD-OPEN1X1M  [JUMP_43X39]  120.57 130.02 180 top
PJP29  PAD-OPEN1X1M  [JUMP_43X39]  89.46 108.75 180 top
PJP30  PAD-OPEN1X1M  [JUMP_43X39]  278.1 66.28 270 top
PJP31  PAD-OPEN1X1M  [JUMP_43X39]  279.12 72.5 270 top
PJP32  PAD-OPEN1X1M  [JUMP_43X39]  159.1 112.51 90 bottom
PJP34  PAD-OPEN1X2M  [JUMP_43X79]  22.53 39.35 90 top
PJP35  PAD-OPEN1X3M  [JUMP_43X118]  169.16 117.76 0 top
PJP36  PAD-OPEN1X2M  [JUMP_43X79]  26.38 39.35 90 top
PJP100  PAD-OPEN 1X2M~D  [JUMP_43X79]  220.58 79.54 90 bottom
PJP101  PAD-OPEN 1X2M~D  [JUMP_43X79]  211.95 79.94 90 bottom
PJP102  -  [JUMP_43X118]  217.33 99.56 90 bottom
PJP103  -  [JUMP_43X118]  211.76 99.7 90 bottom
PJP201  JUMP_1X3M  [JUMP_43X118]  83.24 58.52 0 top
PJP202  PAD-OPEN 1X2M~D  [JUMP_43X79]  67.37 63.03 0 top
PJP203  PAD-OPEN1X1M  [JUMP_43X39]  74.78 72.31 270 bottom
PJP204  JUMP_1X3M  [JUMP_43X118]  83.24 53.31 0 top
PJP205  PAD-OPEN1X1M  [JUMP_43X39]  72.82 74.84 180 bottom
PJP301  PAD-OPEN 1X2M~D  [JUMP_43X79]  226.37 78.96 90 top
PJP302  -  [JUMP_43X118]  224.89 92.96 90 bottom
PJP401  -  [JUMP_43X79]  237.72 52.7 90 top
PJP402  -  [JUMP_43X79]  234.96 90.84 180 top
PJP403  PAD-OPEN1X1M  [JUMP_43X39]  239.1 45.03 270 bottom
PJP404  PAD-OPEN1X1M  [JUMP_43X39]  246.81 89.19 180 top
PJP501  -  [JUMP_43X79]  296.18 4.23 180 top
PJP502  -  [JUMP_43X79]  280.56 3.93 180 top
PJP503  PAD-OPEN1X1M  [JUMP_43X39]  288.69 20.1 0 top
PJP504  PAD-OPEN1X1M  [JUMP_43X39]  296.85 20.17 0 top
PJP601  PAD-OPEN 4X4M  [JUMP_43X118]  97.04 98.21 180 bottom
PJP602  PAD-OPEN 1X2M~D  [JUMP_43X79]  96.75 90.04 90 bottom
PJP603  PAD-OPEN1X1M  [JUMP_43X39]  128.38 110.65 180 bottom
PJP801  PAD-OPEN 4X4M  [JUMP_43X118-NPM]  61.24 54.87 235 bottom
PJP1500  PAD-OPEN1X1M  [JUMP_43X39]  249.11 39.65 180 top
PJP1501  PAD-OPEN1X1M  [JUMP_43X39]  262.52 45.53 180 top
PJPDC1  CVILU_CI0805M1HRC-NH  [CVILU_CI0805M1HRC-NH_5P-T]  77.25 103.8 195 bottom
PL1  FBMJ4516HS720NT_2P  [TAIYO_FBMJ4516HS720NT_2P]  73.25 102.85 270 top
PL2  FBMJ4516HS720NT_2P  [TAIYO_FBMJ4516HS720NT_2P]  71.28 52.36 0 top
PL3  FBMJ4516HS720NT_2P  [TAIYO_FBMJ4516HS720NT_2P]  71.28 54.64 0 top
PL4  BLM15AG102SN1D_2P  [MURAT_BLM15AG102SN1D_2P]  72.36 113.74 270 top
PL100  1.5UH_PCMC063T-1R5MN_9A_20%  [CYNTE_PCMC063T-1R5MN_2P]  216.84 90.53 90 bottom
PL101  2.2UH +-20% 7.8A 7X7X3 MOLDING  [CYNTE_PCMC063T-1R5MN_2P]  209.75 90.72 90 bottom
PL201  1UH_11A_20%  [PANAS_ETQP3W2R2WFN_2P]  73.89 61.91 270 bottom
PL301  0.68UH +-20% 7.9A  [MAG_MMD-05CZ-R68M-X2L_2P]  226.19 85.19 90 bottom
PL402  1UH_1277AS-H-1R0N-P2_3.3A_30%  [MAG_MLV-FY12N1R0M-O1L_2P]  237.14 48.34 90 top
PL404  1UH_1277AS-H-1R0N-P2_3.3A_30%  [MAG_MLV-FY12N1R0M-O1L_2P]  237.69 93.01 270 top
PL501  1UH_1277AS-H-1R0N-P2_3.3A_30%  [MAG_MLV-FY12N1R0M-O1L_2P]  287.56 4.13 180 top
PL601  1UH +-20% 6.6A  [MAG_MMD-05CZ-R68M-X2L_2P]  133.18 113.83 0 bottom
PL602  FBMA-L11-453215800LMA90T_2P  [KC_FBMA-L11-4532158_2P-NPM]  98.39 98.21 180 bottom
PL603  0.15UH_MMD06CZER15MG_37A_20%  [MAG_MMD06CZER15MG_4P]  117.57 101.51 180 bottom
PL604  0.15UH_MMD06CZER15MG_37A_20%  [MAG_MMD06CZER15MG_4P]  108.13 80.44 180 bottom
PL801  3.3UH_10A_20%  [TOKO_FDVE1040-H-3R3M-P3_2P]  44.6 46.45 0 bottom
PL802  1UH +-20% 6.6A  [MAG_MMD-05CZ-R68M-X2L_2P]  59.75 52.74 55 bottom
PQ1  DCX124EK-7-F PNP/NPN_SC74-6~D  [IMD2AT-108_SC74-6]  77.5 98.02 270 top
PQ2  LP2301ALT1G_SOT23-3  [SI2301CDS-T1-GE3_SOT23-3]  70.18 42.63 0 top
PQ3  -  [FDV301N-G_SOT23-3]  73.16 118.46 270 top
PQ4  MMBT3904WT1G NPN SC70-3  [MMST3904-7-F_SOT323-3]  68.68 114.78 0 top
PQ5  AON7401 1P DFN3*3  [FDMC6679AZ_MLP8-5]  71.94 96.43 180 top
PQ201  -  [AON6932A_DFN5X6-8-7]  70.38 67.49 270 top
PQ501  AON7934_DFN3X3A-8-10  [AON7934_DFN3X3A8-10]  130.61 112.45 180 bottom
PQ801  DMP3056L-7 1P SOT23-3  [NTR4502PT1G_SOT23-3]  16.41 52.51 90 bottom
PQ802  -  [SI4835DDY-T1-GE3_SO8]  11.78 52.64 180 bottom
PQ803  DMP3056L-7 1P SOT23-3  [NTR4502PT1G_SOT23-3]  16.41 48.52 90 bottom
PQ804  DMP3056L-7 1P SOT23-3  [NTR4502PT1G_SOT23-3]  17.17 46.4 270 top
PQ805  DMP3056L-7 1P SOT23-3  [NTR4502PT1G_SOT23-3]  17.17 50.4 270 top
PQ808  AON6992 2N DFN5X6D  [AON6932A_DFN5X6-8-7]  58.09 43.1 90 top
PQ809  L2N7002WT1G_SC70-3  [DMN65D8LW-7_SOT323-3]  62.27 59.72 270 bottom
PQ901  -  [FDS6679AZ-G_SO8]  21.05 39.52 180 bottom
PQ902  S TR DMN65D8LDW-7 2N SOT363-6  [DMN65D8LDW-7_SOT363-6]  64.17 70.28 270 top
PQ903  -  [SI4835DDY-T1-GE3_SO8]  28.19 43.2 270 bottom
PQ904  -  [FDS6679AZ-G_SO8]  7.9 49.84 0 bottom
PQ905  AON7401 1P DFN3*3  [FDMC6679AZ_MLP8-5]  15.36 43.15 180 bottom
PQ906  L2N7002WT1G_SC70-3  [DMN65D8LW-7_SOT323-3]  95.93 75.26 270 top
PQ907  S TR DMN65D8LDW-7 2N SOT363-6  [DMN65D8LDW-7_SOT363-6]  103.03 72.54 90 top
PQ908  L2N7002WT1G_SC70-3  [DMN65D8LW-7_SOT323-3]  16.86 40.23 180 top
PQ909  LP2301ALT1G_SOT23-3  [SI2301CDS-T1-GE3_SOT23-3]  97.61 73.59 180 top
PQ910  -  [DMP3099L-7_SOT23-3]  9.98 54.14 270 top
PQ911  S TR DMN65D8LDW-7 2N SOT363-6  [DMN65D8LDW-7_SOT363-6]  8.17 57.05 90 top
PR1  1M_0402_5%  [R_0402]  77.75 101.25 0 top
PR2  1K_0402_5%  [R_0402]  281.1 16.25 270 bottom
PR3  100K_0402_5%  [R_0402]  70.28 39.15 180 top
PR4  0_0402_5%  [R0402_0OHM]  72.62 42.76 90 top
PR5  0_0402_5%  [R_0402]  73.43 120.94 0 top
PR6  2.2K_0402_5%  [R_0402]  76.98 120.94 0 top
PR7  33_0402_5%  [R_0402]  75.21 120.94 0 top
PR8  100K_0402_1%  [R_0402]  70.44 116.37 0 top
PR9  10K_0402_1%  [R_0402]  71.35 114.51 90 top
PR10  15K_0402_1%  [R_0402]  71.36 117.26 180 top
PR11  10K_0402_5%  [R_0402]  70.46 115.43 270 top
PR12  100K_0402_5%  [R_0402]  71.73 91.17 270 top
PR13  4.7K_0805_5%  [R_0805]  75.35 98.87 270 top
PR14  10K_0402_5%  [R_0402]  80.49 101.24 90 top
PR15  1M_0402_5%  [R_0402]  79.6 101.24 90 top
PR100  0_0603_5%  [R0603_0OHM]  219.99 87.8 90 top
PR101  0_0402_5%  [R_0402]  205.03 79.22 270 top
PR102  499K_0402_1%  [R_0402]  214.35 79.69 270 bottom
PR103  499K_0402_1%  [R_0402]  214.34 80.56 0 bottom
PR104  0_0402_5%  [R0402_0OHM]  213.42 85.85 270 top
PR105  0_0402_5%  [R0402_0OHM]  212.54 85.85 270 top
PR106  4.7_1206_5%  [R_1206]  217.14 89.65 270 top
PR107  100K_0402_5%  [R_0402]  215.24 82.29 90 bottom
PR108  1K_0402_5%  [R_0402]  212.38 85.89 0 bottom
PR109  150K_0402_1%  [R_0402]  214.18 85.92 270 bottom
PR110  150K_0402_1%  [R_0402]  213.29 84.11 180 bottom
PR111  0_0603_5%  [R0603_0OHM]  212.13 87.02 0 bottom
PR112  4.7_1206_5%  [R_1206]  209.4 87.88 0 top
PR113  100K_0402_5%  [R_0402]  207.29 83.5 270 bottom
PR114  0_0402_5%  [R0402_0OHM]  205.18 80.89 0 bottom
PR115  150K_0402_1%  [R_0402]  205.7 86.32 270 bottom
PR116  1M_0402_1%  [R_0402]  206.09 81.78 180 bottom
PR117  1K_0402_5%  [R_0402]  204.78 87.19 0 bottom
PR118  150K_0402_1%  [R_0402]  205.17 84.49 270 bottom
PR119  0_0402_5%  [R0402_0OHM]  207.39 79.19 270 top
PR120  0_0402_5%  [R0402_0OHM]  206.47 79.19 270 top
PR201  2.2_0603_5%  [R_0603]  80.62 77.38 90 bottom
PR202  2.2_0603_5%  [R_0603]  76.81 71.15 90 bottom
PR203  5.1K_0402_1%  [R_0402]  80.19 76.23 180 bottom
PR204  4.7_1206_5%  [R_1206]  72.93 69.44 0 top
PR205  5.1_0603_5%  [R_0603]  80.89 73.81 90 bottom
PR206  12K_0402_1%  [R_0402]  76.74 79.49 90 top
PR207  453K_0402_1%  [R_0402]  77.95 80.37 270 bottom
PR208  0_0402_5%  [R0402_0OHM]  77.06 80.37 270 bottom
PR209  20K_0402_1%  [R_0402]  75.16 78.2 270 top
PR210  0_0402_5%  [R0402_0OHM]  76.17 80.37 270 bottom
PR301  0_0402_5%  [R_0402]  230.59 89.06 0 top
PR302  1M_0402_1%  [R_0402]  230.59 88.17 0 top
PR303  4.7_1206_5%  [R_1206]  222.6 82.65 90 bottom
PR304  0_0603_5%  [R0603_0OHM]  225.46 82.58 180 bottom
PR306  6.65K_0402_1%  [R_0402]  231.51 85.51 180 top
PR307  0_0402_5%  [R_0402]  231.51 86.39 180 top
PR308  1K_0402_5%  [R_0402]  230.6 83.65 90 top
PR310  0_0402_5%  [R_0402]  230.59 87.28 0 top
PR311  10K_0402_1%  [R_0402]  229.72 84.57 270 top
PR312  0_0402_5%  [R0402_0OHM]  229.72 88.16 90 top
PR402  0_0402_5%  [R0402_0OHM]  242.5 44.08 180 top
PR403  1M_0402_1%  [R_0402]  241.59 43.21 270 top
PR404  0_0402_5%  [R_0402]  242.48 45.89 270 top
PR405  4.7_0603_5%  [R_0603]  239.43 48.29 0 top
PR406  0_0402_5%  [R0402_0OHM]  245.27 96.12 270 top
PR407  1M_0402_1%  [R_0402]  244.38 95.21 90 top
PR408  0_0402_5%  [R_0402]  244.88 86.52 90 top
PR409  4.7_0603_5%  [R_0603]  237.4 94.78 0 top
PR410  0_0402_5%  [R_0402]  242.61 96.12 270 top
PR411  0_0402_5%  [R_0402]  243.99 86.52 90 top
PR412  0_0402_5%  [R0402_0OHM]  234.05 43.6 180 top
PR413  10K_0402_1%  [R_0402]  232.06 40.81 0 top
PR414  10K_0402_1%  [R_0402]  232.06 39.87 270 top
PR415  10K_0402_1%  [R_0402]  233.94 41.8 270 top
PR416  10K_0402_1%  [R_0402]  232.97 38.96 90 top
PR417  10K_0402_1%  [R_0402]  243.1 86.52 90 top
PR418  10K_0402_1%  [R_0402]  245.77 86.52 90 top
PR419  10K_0402_1%  [R_0402]  243.05 88.31 180 top
PR420  10K_0402_1%  [R_0402]  246.69 87.44 270 top
PR421  100_0402_1%  [R_0402]  233.13 45.37 0 top
PR422  0_0402_5%  [R0402_0OHM]  234.05 44.48 180 top
PR423  0_0402_5%  [R0402_0OHM]  240.33 88.81 180 top
PR424  100K_0402_1%  [R_0402]  240.33 87.85 180 top
PR425  0_0402_5%  [R_0402]  241.59 45.89 270 top
PR426  0_0402_5%  [R_0402]  241.72 96.12 270 top
PR427  0_0402_5%  [R0402_0OHM]  232.98 41.74 180 top
PR428  1M_0402_1%  [R_0402]  241.32 86.56 0 top
PR501  20K_0402_1%  [R_0402]  293.6 7.6 270 top
PR502  4.7_0603_5%  [R_0603]  288.71 3.34 0 top
PR504  0_0402_5%  [R0402_0OHM]  285.89 7.72 270 top
PR505  1M_0402_1%  [R_0402]  286.78 6.8 90 top
PR506  10K_0402_1%  [R_0402]  294.49 6.69 90 top
PR507  100K_0402_5%  [R_0402]  288.19 13.5 0 top
PR508  8.87K_0402_1%  [R_0402]  298.68 16.87 270 top
PR509  47K_0402_5%  [R_0402]  289.1 14.39 180 top
PR510  10.2K_0402_1%  [R_0402]  297.84 15.02 0 top
PR511  47K_0402_5%  [R_0402]  289.1 12.58 180 top
PR601  45.3_0402_1%  [R_0402]  82.73 87.03 180 bottom
PR602  0_0402_5%  [R0402_0OHM]  84.24 89.56 90 bottom
PR603  0_0402_5%  [R0402_0OHM]  81.57 89.75 90 bottom
PR604  75_0402_1%  [R_0402]  82.73 87.92 180 bottom
PR605  100_0402_1%  [R_0402]  82.73 88.81 180 bottom
PR606  0_0402_5%  [R0402_0OHM]  79.46 87.03 0 bottom
PR607  0_0402_5%  [R0402_0OHM]  79.46 87.92 0 bottom
PR608  78.7K_0402_1%  [R_0402]  82.73 89.82 180 top
PR609  0_0402_5%  [R0402_0OHM]  79.46 88.81 0 bottom
PR610  10K_0402_1%  [R_0402]  84.67 83.22 0 top
PR611  48.7K_0402_1%  [R_0402]  82.73 90.71 180 top
PR612  1.91K_0402_1%  [R_0402]  81.81 86.14 0 top
PR613  90.9K_0402_1%  [R_0402]  84.49 86.09 270 bottom
PR614  0_0402_5%  [R0402_0OHM]  81.81 85.25 0 top
PR616  0_0402_5%  [R0402_0OHM]  81.81 84.36 0 top
PR617  4.3K_0402_1%  [R_0402]  87.16 86.09 270 bottom
PR618  49.9_0402_1%  [R_0402]  81.81 87.16 0 top
PR619  2.2_0603_5%  [R_0603]  129.19 113.83 0 top
PR620  0_0402_5%  [R0402_0OHM]  82.84 82.38 90 top
PR621  316_0402_1%  [R_0402]  86.46 81.43 90 top
PR622  1.96K_0402_1%  [R_0402]  87.36 83.22 180 top
PR623  2K_0402_1%  [R_0402]  85.57 81.43 90 top
PR624  3.65K_0603_1%  [R_0603]  134.53 117.34 180 bottom
PR625  0_0402_5%  [R0402_0OHM]  81.81 88.05 0 top
PR626  10_0402_1%  [R_0402]  81.81 88.93 0 top
PR627  4.7_1206_5%  [R_1206]  131.86 115.29 0 top
PR628  4.42K_0402_1%  [R_0402]  99.88 84.97 0 bottom
PR629  88.7K_0402_1%  [R_0402]  88.92 85.7 0 bottom
PR630  7.32K_0402_1%  [R_0402]  86.03 90.46 180 bottom
PR631  27.4K_0402_1%  [R_0402]  83.79 82.32 90 top
PR632  1K_0402_1%  [R_0402]  89.14 81.44 180 top
PR633  11K_0402_1%  [R_0402]  82.71 80.76 270 bottom
PR635  10K_0402_1%  [R_0402]  91.6 87.87 270 bottom
PR636  1.24K_0402_1%  [R_0402]  85.13 92.54 90 top
PR638  374_0402_1%  [R_0402]  89.13 82.32 90 top
PR639  5.49K_0402_1%  [R_0402]  88.92 88.36 0 bottom
PR640  340_0402_1%  [R_0402]  92.61 91.28 0 top
PR641  1K_0402_1%  [R_0402]  86.03 94.33 180 top
PR642  2.61K_0402_1%  [R_0402]  134.67 118.45 0 bottom
PR643  11K_0402_1%  [R_0402]  85.06 93.52 270 bottom
PR644  1K_0402_1%  [R_0402]  92.61 92.17 0 top
PR645  316_0402_1%  [R_0402]  93.58 87.73 180 top
PR646  316_0402_1%  [R_0402]  88.68 92.6 90 top
PR647  27.4K_0402_1%  [R_0402]  93.39 87.85 180 bottom
PR648  1.37K_0402_1%  [R_0402]  91.79 88.63 270 top
PR649  1.62K_0402_1%  [R_0402]  87.81 92.62 180 top
PR650  2K_0402_1%  [R_0402]  93.36 86.05 90 bottom
PR651  133K_0402_1%  [R_0402]  88.68 90.53 270 bottom
PR652  2K_0402_1%  [R_0402]  89.57 92.6 90 top
PR653  20M_0402_5%  [R_0402]  90.87 91.96 270 bottom
PR654  20M_0402_5%  [R_0402]  84.84 91.76 0 bottom
PR656  11K_0402_1%  [R_0402]  91.72 90.39 0 bottom
PR657  4.42K_0402_1%  [R_0402]  110.2 95.92 0 bottom
PR658  20M_0402_5%  [R_0402]  83.41 80.5 0 top
PR659  0_0402_5%  [R0402_0OHM]  107.64 105.43 0 bottom
PR660  2.2_0603_5%  [R_0603]  103.16 107.1 270 top
PR661  3.65K_0603_1%  [R_0603]  111.61 97.06 180 bottom
PR662  5.11K_0402_1%  [R_0402]  102.38 105.32 0 bottom
PR663  4.7_1206_5%  [R_1206]  107.54 102.97 90 top
PR671  0_0402_5%  [R0402_0OHM]  95.59 82.66 180 bottom
PR672  2.2_0603_5%  [R_0603]  88.03 79.05 0 top
PR673  0_0402_5%  [R0402_0OHM]  100.51 81.24 90 top
PR674  3.65K_0603_1%  [R_0603]  99.37 82.43 270 top
PR676  4.7_1206_5%  [R_1206]  100.63 78.95 180 top
PR678  100_0402_1%  [R_0402]  79.98 85.71 270 top
PR679  0_0402_5%  [R0402_0OHM]  127.24 114.97 180 top
PR680  5.11K_0402_1%  [R_0402]  90.56 82.43 0 bottom
PR801  100K_0402_1%  [R_0402]  53.76 57.17 90 bottom
PR802  0.01_1206_1%  [R_1206_4P-D]  14.01 48.55 90 bottom
PR803  100K_0402_1%  [R_0402]  6.45 56.73 90 bottom
PR804  0_0402_5%  [R0402_0OHM]  17.21 55.1 180 bottom
PR805  100_0402_1%  [R_0402]  20.29 49.74 90 bottom
PR806  0_0402_5%  [R0402_0OHM]  21.17 50.64 0 bottom
PR807  0_0402_5%  [R0402_0OHM]  21.17 49.75 0 bottom
PR808  100K_0402_1%  [R_0402]  21.05 46.31 90 top
PR809  100K_0402_1%  [R_0402]  21.05 49.01 270 top
PR810  0_0402_5%  [R0402_0OHM]  21.94 47.2 90 top
PR811  10_1206_5%  [R_1206]  60.55 52.71 180 top
PR812  34K_0402_1%  [R_0402]  58.2 57.17 90 bottom
PR813  6.49K_0402_1%  [R_0402]  56.63 56.3 180 bottom
PR814  2.2_0603_5%  [R_0603]  54.52 51.28 270 top
PR815  0_0402_5%  [R0402_0OHM]  58.07 58.21 270 top
PR816  0_0402_5%  [R0402_0OHM]  57.31 60.37 270 top
PR817  154K_0402_1%  [R_0402]  54.65 58.09 270 bottom
PR818  100_0402_1%  [R_0402]  54.65 60.37 270 top
PR819  0_0402_5%  [R0402_0OHM]  56.42 60.37 270 top
PR820  0_0402_5%  [R0402_0OHM]  55.53 60.37 270 top
PR821  10K_0402_1%  [R_0402]  51.28 52.05 270 top
PR822  31.6K_0402_1%  [R_0402]  55.53 57.17 90 bottom
PR823  0.01_1206_1%  [R_1206_4P-D]  34.41 46.22 0 bottom
PR824  4.7_1206_5%  [R_1206]  52.04 40.17 0 top
PR825  4.02K_0402_1%  [R_0402]  50.66 55.22 180 top
PR826  10_0603_1%  [R_0603]  50.29 56.33 180 top
PR827  1K_0402_5%  [R_0402]  52.69 57.69 180 bottom
PR828  0_0402_5%  [R0402_0OHM]  49.36 58.77 0 top
PR829  154K_0402_1%  [R_0402]  51.78 56.8 0 bottom
PR830  649K_0402_1%  [R_0402]  62.28 60.44 270 top
PR831  100K_0402_1%  [R_0402]  60.17 60.44 270 top
PR832  3M_0402_5%  [R_0402]  61.06 59.52 90 top
PR833  0_0402_5%  [R0402_0OHM]  61.06 62.34 270 top
PR834  10K_0402_1%  [R_0402]  60.17 61.43 90 top
PR835  0_0402_5%  [R0402_0OHM]  52.87 60.37 270 top
PR836  0_0402_5%  [R0402_0OHM]  53.76 60.37 270 top
PR837  1M_0402_1%  [R_0402]  92.92 74.13 90 top
PR901  0_0402_5%  [R0402_0OHM]  93.37 71.92 0 top
PR902  100K_0402_5%  [R_0402]  65.58 67.85 180 top
PR903  100K_0402_5%  [R_0402]  67.16 70.47 270 top
PR904  0_0402_5%  [R_0402]  64.67 66.96 0 top
PR905  100K_0402_5%  [R_0402]  67.16 71.33 90 top
PR906  0_0402_5%  [R0402_0OHM]  6.62 46.09 180 bottom
PR907  0_0402_5%  [R0402_0OHM]  67.16 74.02 270 top
PR908  330K_0402_5%  [R_0402]  9.67 42.91 0 bottom
PR909  100K_0402_5%  [R_0402]  100.05 72.6 90 top
PR910  100K_0402_5%  [R_0402]  14.12 41.82 0 top
PR911  100K_0402_5%  [R_0402]  9.12 55.71 90 top
PR912  10K_0402_5%  [R_0402]  14.12 40.04 0 top
PR913  0_0402_5%  [R0402_0OHM]  98.85 69.76 180 top
PR914  100K_0402_5%  [R_0402]  104.11 72.86 90 top
PR915  100K_0402_5%  [R_0402]  97.08 69.76 180 top
PR916  10K_0402_5%  [R_0402]  92.05 74.13 90 top
PR917  100K_0402_5%  [R_0402]  8.3 59.47 180 top
PR918  0_0402_5%  [R0402_0OHM]  91.41 63.08 90 top
PR919  0_0402_5%  [R0402_0OHM]  5.18 58.66 270 top
PR920  100K_0402_5%  [R_0402]  88.29 63.15 0 top
PR921  47_0805_5%~D  [R_0805]  84.32 63.05 0 top
PR922  0_0402_5%  [R0402_0OHM]  87.6 74.13 90 top
PR923  0_0402_5%  [R0402_0OHM]  89.2 64.04 180 top
PR924  100_0603_1%  [R_0603]  84.11 69 180 top
PR925  10K_0402_5%  [R_0402]  84.92 74.68 90 top
PR926  0_0402_5%  [R0402_0OHM]  90.27 74.13 90 top
PR927  0_0402_5%  [R_0402]  91.16 74.13 90 top
PR928  100_0603_1%  [R_0603]  90.27 62.71 90 top
PR929  1M_0402_5%  [R_0402]  89.38 75.04 270 top
PR930  0_0402_5%  [R0402_0OHM]  86.71 74.13 90 top
PR931  0_0402_5%  [R0402_0OHM]  93.37 72.81 0 top
PR932  0_0402_5%  [R0402_0OHM]  92.3 63.08 90 top
PR933  100_0603_1%  [R_0603]  84.11 71.15 180 top
PR934  1M_0402_5%  [R_0402]  93.37 71.03 0 top
PR935  100_0603_1%  [R_0603]  82.71 67.73 0 top
PR936  100K_0402_5%  [R_0402]  8.05 55.66 180 top
PR937  0_0402_5%  [R0402_0OHM]  85.82 74.13 90 top
PR938  0_0402_5%  [R0402_0OHM]  88.49 74.13 90 top
PR939  100_0603_1%  [R_0603]  93.38 69.88 0 top
PR1500  47K_0402_5%  [R_0402]  251.7 43.56 0 top
PR1501  21.5K_0402_1%  [R_0402]  251.98 39.86 0 top
PR1502  47K_0402_5%  [R_0402]  252.87 44.43 180 top
PR1503  10.2K_0402_1%  [R_0402]  252.64 41.46 90 top
PRP1  100_0804_8P4R_5%  [RP_0804_8P4R]  66.02 44.8 90 top
PU1  TS5A63157DCKR_SC70-6~D  [TS5A63157DCKR_SC70-6]  75.75 114.57 90 top
PU100  SY8288BRAC_QFN20_3X3  [SY8286BRAC_QFN20_3X3]  218.91 87 180 bottom
PU101  TC7SH08FU_SSOP5~D  [TC7SH08FU_SSOP5]  206.01 80.64 0 top
PU102  -  [SY8286CRAC_QFN20_3X3]  210.59 87.34 180 bottom
PU201  -  [RT8207PGQW_WQFN20_3X3]  74.52 75.41 90 bottom
PU301  -  [SYX196DQNC_QFN10_3X3]  227.83 84.46 270 top
PU401  SY8057QDC QFN  [TPS62134CRGT_QFN16_3X3]  238.43 46.66 270 top
PU402  SY8057QDC QFN  [TPS62134BRGT_QFN16_3X3]  240.15 92.57 0 top
PU501  -  [SY8032ABC_SOT23-6]  288.97 6.7 270 top
PU502  -  [AP7175SP-13_SO-8EP-8]  295.93 14.41 90 top
PU602  ISL95857HRTZ-T_TQFN40_5X5  [ISL62883CHRTZ-T_TQFN40_5X5]  85.32 85.38 0 top
PU603  -  [CSD97374CQ4M_SON8_3P5X4P5]  106.24 104 270 bottom
PU605  -  [CSD97374CQ4M_SON8_3P5X4P5]  95.36 81.06 270 bottom
PU606  -  [ISL95808HRZ-TS2378_DFN8_2X2]  124.5 113.83 90 bottom
PU801  BQ24777RUYR_WQFN28_4X4  [BQ24715URUYR_WQFN28_4X4]  56.11 54.26 180 top
PU901  CD3301BRHHR_QFN36_6X6~D  [CD3301RHHR_QFN36_6X6]  86.69 66.24 0 top
PU902  TC7SH08FU_SSOP5~D  [TC7SH08FU_SSOP5]  66.03 73.75 180 top
PU903  TC7SH08FU_SSOP5~D  [TC7SH08FU_SSOP5]  101.13 70.92 270 top
PU1500  -  [AP7175SP-13_SO-8EP-8]  254.06 39.65 0 top
QA1  -  [L2N7002WT1G_SC-70-3]  282.22 64.16 0 top
QA2  -  [DMN65D8LDW-7_SOT363-6]  297.32 73.19 0 top
QA3  -  [DMN65D8LDW-7_SOT363-6]  279.13 52.91 90 top
QC2  -  [DMN65D8LDW-7_SOT363-6]  178.44 96.27 90 top
QC3  -  [L2N7002WT1G_SC-70-3]  180.41 87.75 90 bottom
QE2  -  [DMN65D8LDW-7_SOT363-6]  249.36 55.53 90 top
QE3  MMBT3904WT1G_SC70-3~D  [MMBT3904WT1G_SC70-3]  139.29 89.95 270 top
QE4  MMBT3904WT1G_SC70-3~D  [MMBT3904WT1G_SC70-3]  257.72 56.42 270 top
QE5  MMBT3904WT1G_SC70-3~D  [MMBT3904WT1G_SC70-3]  222.03 53.76 270 top
QE6  MMBT3904WT1G_SC70-3~D  [MMBT3904WT1G_SC70-3]  110.59 102.78 0 top
QE7  MMBT3904WT1G_SC70-3~D  [MMBT3904WT1G_SC70-3]  269.85 63.47 180 bottom
QE11  -  [L2N7002WT1G_SC-70-3]  265.87 52.98 90 top
QL1  -  [DMN65D8LDW-7_SOT363-6]  285.92 119.3 270 top
QL2  -  [DMN65D8LDW-7_SOT363-6]  286 115.45 90 top
QR1  -  [L2N7002WT1G_SC-70-3]  270.92 61.38 90 bottom
QV1  -  [AO6405_TSOP6]  90.97 114.11 180 top
QV2  -  [L2N7002WT1G_SC-70-3]  85.06 115.16 0 top
QV3  -  [DMN65D8LDW-7_SOT363-6]  240.44 126.8 270 bottom
QV4  -  [L2N7002WT1G_SC-70-3]  238.29 128.18 90 top
QV5  -  [L2N7002WT1G_SC-70-3]  247.56 131.86 270 bottom
QV7  -  [L2N7002WT1G_SC-70-3]  106.43 113.72 325 top
QV8  -  [LP2301ALT1G_SOT23-3]  102.5 116.58 235 top
QV9  -  [L2N7002WT1G_SC-70-3]  206.47 123.04 0 bottom
QV10  -  [L2N7002WT1G_SC-70-3]  206.47 117.45 0 bottom
QZ1  -  [LP2301ALT1G_SOT23-3]  100.59 111.19 325 top
QZ3  -  [DMN65D8LDW-7_SOT363-6]  280.07 18.21 270 top
QZ4  -  [DDTA114EUA-7-F_SOT323-3]  282.64 19.47 270 top
QZ7  -  [DMN65D8LDW-7_SOT363-6]  280.33 22.66 270 top
QZ9  -  [LP2301ALT1G_SOT23-3]  218.82 78.42 180 top
R6  10_0402_5%  [R_0402]  154.02 127.11 270 bottom
R41  10_0402_5%  [R_0402]  156.73 127.11 270 bottom
R252  33_0402_5%  [R_0402]  137.89 126.2 90 bottom
R253  33_0402_5%  [R_0402]  138.78 126.2 90 bottom
R254  33_0402_5%  [R_0402]  138.53 136.13 270 top
R255  33_0402_5%  [R_0402]  139.67 126.2 90 bottom
R256  33_0402_5%  [R_0402]  139.42 136.13 270 top
R257  33_0402_5%  [R_0402]  140.56 126.2 90 bottom
R258  33_0402_5%  [R_0402]  142.09 136.13 270 top
R259  33_0402_5%  [R_0402]  137.01 126.2 90 bottom
R260  33_0402_5%  [R_0402]  136.75 136.13 270 top
R261  33_0402_5%  [R_0402]  137.64 136.13 270 top
R262  33_0402_5%  [R_0402]  140.31 136.13 270 top
R263  33_0402_5%  [R_0402]  141.45 126.2 90 bottom
R264  33_0402_5%  [R_0402]  141.2 136.13 270 top
R265  33_0402_5%  [R_0402]  142.34 126.2 90 bottom
R266  33_0402_5%  [R_0402]  143.23 126.2 90 bottom
R267  33_0402_5%  [R_0402]  142.97 136.13 270 top
R268  100K_0402_5%  [R_0402]  144.12 127.11 270 bottom
R271  100K_0402_5%  [R_0402]  144.75 136.13 270 top
R272  100K_0402_5%  [R_0402]  176.01 122.42 90 bottom
R273  10_0402_5%  [R_0402]  166.09 127.11 270 bottom
R274  0_0603_5%  [R0603_0OHM]  265.86 85 180 top
RA1  10K_0402_5%  [R_0402]  284.5 40.72 90 top
RA2  100K_0402_5%  [R_0402]  284.5 43.42 270 top
RA3  0_0603_5%  [R0603_0OHM]  291.06 79.6 270 top
RA4  0_0603_5%  [R0603_0OHM]  293.47 79.6 270 top
RA5  2.2K_0402_5%  [R_0402]  294.68 64.09 90 top
RA6  2.2K_0402_5%  [R_0402]  293.76 64.09 90 top
RA7  24.9_0402_1%  [R_0402]  293.93 71.9 0 top
RA8  24.9_0402_1%  [R_0402]  293.93 71.01 0 top
RA9  33_0402_5%  [R_0402]  283.29 68.99 0 top
RA12  1K_0402_5%  [R_0402]  285.18 63.09 270 top
RA13  1K_0402_5%  [R_0402]  284.29 63.09 270 top
RA14  33_0402_5%  [R_0402]  284.4 73.95 180 top
RA17  33_0402_5%  [R_0402]  283.57 70.33 180 top
RA18  10K_0402_5%  [R_0402]  283.49 74.96 0 top
